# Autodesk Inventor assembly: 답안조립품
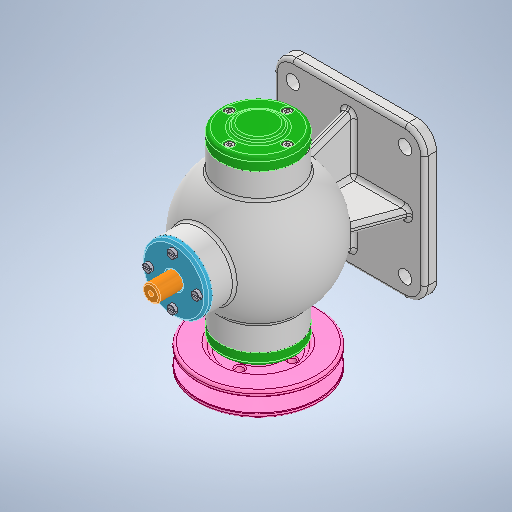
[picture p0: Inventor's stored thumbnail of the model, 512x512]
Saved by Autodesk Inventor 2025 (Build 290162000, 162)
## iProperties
Created: 2025-08
Part Number: 답안조립품
Document SubType Name: Assembly
Designer: infra02
Author: infra02
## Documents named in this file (15)
- C:\Users\infra02\Desktop\750807V1004\답안조립품.iam
- C:\Users\infra02\Desktop\750807V1004\본체.ipt
- C:\Users\infra02\Desktop\750807V1004\편심축\편심축.ipt
- C:\Users\infra02\Desktop\750807V1004\앞커버\앞커버.ipt
- C:\Users\infra02\Desktop\750807V1004\볼트 M4 x 16\볼트 M4 x 16.ipt
- C:\Users\infra02\Desktop\750807V1004\뒤커버\뒤커버.ipt
- C:\Users\infra02\Desktop\750807V1004\오일실 15 30 7\오일실 15 30 7.ipt
- C:\Users\infra02\Desktop\750807V1004\V-벨트풀리\V-벨트풀리.ipt
- C:\Users\infra02\Desktop\750807V1004\너트 M8\너트 M8.ipt
- C:\Users\infra02\Desktop\750807V1004\베어링- 6202\베어링- 6202.ipt
- C:\Users\infra02\Desktop\750807V1004\볼트 M4 x 12\볼트 M4 x 12.ipt
- C:\Users\infra02\Desktop\750807V1004\상부커버\상부커버.ipt
- C:\Users\infra02\Desktop\750807V1004\슬라이드\슬라이드.ipt
- C:\Users\infra02\Desktop\750807V1004\칼라\칼라.ipt
- C:\Users\infra02\Desktop\750807V1004\키 4 x 4 x 12\키 4 x 4 x 12.ipt
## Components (1 placed, 1 different names)
1. V-벨트풀리:1
